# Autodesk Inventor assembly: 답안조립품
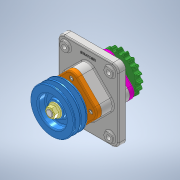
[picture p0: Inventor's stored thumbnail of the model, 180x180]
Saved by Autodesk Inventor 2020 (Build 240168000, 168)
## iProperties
Created: 2021-07
Part Number: 답안조립품
Document SubType Name: Assembly
Designer: Owner
Author: Owner
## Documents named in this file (16)
- C:\Users\Owner\Desktop\710707V1017\답안조립품.iam
- C:\Users\Owner\Desktop\710707V1017\본체.ipt
- C:\Users\Owner\Desktop\710707V1017\M16 너트.ipt
- C:\Users\Owner\Desktop\710707V1017\V-벨트풀리.ipt
- C:\Users\Owner\Desktop\710707V1017\멈춤나사 M4.ipt
- C:\Users\Owner\Desktop\710707V1017\베어링 6206.ipt
- C:\Users\Owner\Desktop\710707V1017\볼트 M6.ipt
- C:\Users\Owner\Desktop\710707V1017\부시.ipt
- C:\Users\Owner\Desktop\710707V1017\오일실 30x42x8.ipt
- C:\Users\Owner\Desktop\710707V1017\오일실 30x45x8.ipt
- C:\Users\Owner\Desktop\710707V1017\체인 스프로킷.ipt
- C:\Users\Owner\Desktop\710707V1017\축.ipt
- C:\Users\Owner\Desktop\710707V1017\커버A.ipt
- C:\Users\Owner\Desktop\710707V1017\커버B.ipt
- C:\Users\Owner\Desktop\710707V1017\키 6x6x18.ipt
- C:\Users\Owner\Desktop\710707V1017\키 6x6x20.ipt
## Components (3 placed, 2 different names)
1. M16 너트:1 — 각도:4
2. V-벨트풀리:1 — 각도:1, 각도:4
3. M16 너트:2 — 각도:3
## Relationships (3: Angle 3)
- 각도:1 [Angle]: V-벨트풀리:1
- 각도:3 [Angle]: M16 너트:2
- 각도:4 [Angle]: M16 너트:1 ↔ V-벨트풀리:1
